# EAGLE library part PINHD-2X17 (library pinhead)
PIN HEADER
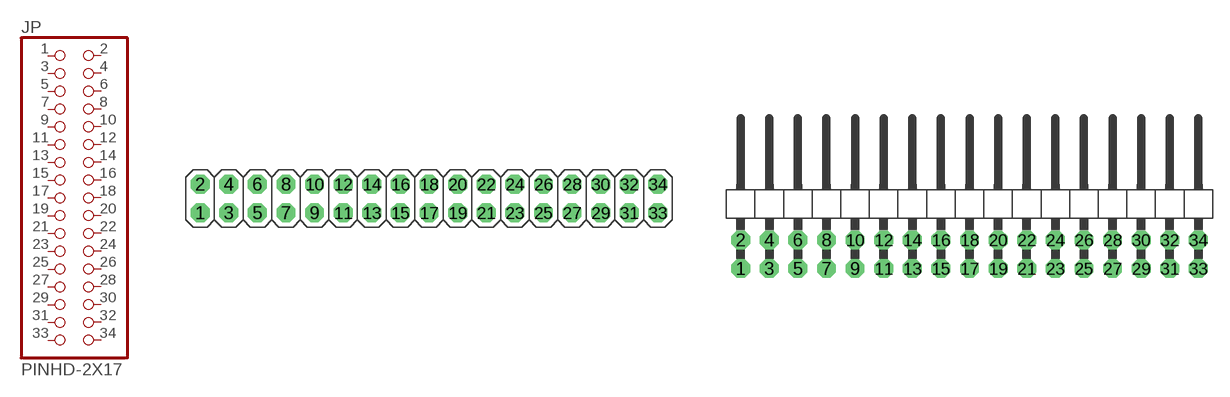
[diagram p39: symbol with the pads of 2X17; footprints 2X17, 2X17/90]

Designator prefix JP

## PINHD-2X17  [2X17]
1  1  pas
2  2  pas
3  3  pas
4  4  pas
5  5  pas
6  6  pas
7  7  pas
8  8  pas
9  9  pas
10  10  pas
11  11  pas
12  12  pas
13  13  pas
14  14  pas
15  15  pas
16  16  pas
17  17  pas
18  18  pas
19  19  pas
20  20  pas
21  21  pas
22  22  pas
23  23  pas
24  24  pas
25  25  pas
26  26  pas
27  27  pas
28  28  pas
29  29  pas
30  30  pas
31  31  pas
32  32  pas
33  33  pas
34  34  pas

## PINHD-2X17/90  [2X17/90]
Pads as for 2X17

## Footprint 2X17 (pad centres in mm)
PIN HEADER
drill 1.016 pad 1.67 octagon: 1 -20.32,-1.27; 2 -20.32,1.27; 3 -17.78,-1.27; 4 -17.78,1.27; 5 -15.24,-1.27; 6 -15.24,1.27; 7 -12.7,-1.27; 8 -12.7,1.27; 9 -10.16,-1.27; 10 -10.16,1.27; 11 -7.62,-1.27; 12 -7.62,1.27; 13 -5.08,-1.27; 14 -5.08,1.27; 15 -2.54,-1.27; 16 -2.54,1.27; 17 0,-1.27; 18 0,1.27; 19 2.54,-1.27; 20 2.54,1.27; 21 5.08,-1.27; 22 5.08,1.27; 23 7.62,-1.27; 24 7.62,1.27; 25 10.16,-1.27; 26 10.16,1.27; 27 12.7,-1.27; 28 12.7,1.27; 29 15.24,-1.27; 30 15.24,1.27; 31 17.78,-1.27; 32 17.78,1.27; 33 20.32,-1.27; 34 20.32,1.27

## Footprint 2X17/90 (pad centres in mm)
PIN HEADER
drill 1.016 pad 1.67 octagon: 1 -20.32,-6.35; 2 -20.32,-3.81; 3 -17.78,-6.35; 4 -17.78,-3.81; 5 -15.24,-6.35; 6 -15.24,-3.81; 7 -12.7,-6.35; 8 -12.7,-3.81; 9 -10.16,-6.35; 10 -10.16,-3.81; 11 -7.62,-6.35; 12 -7.62,-3.81; 13 -5.08,-6.35; 14 -5.08,-3.81; 15 -2.54,-6.35; 16 -2.54,-3.81; 17 0,-6.35; 18 0,-3.81; 19 2.54,-6.35; 20 2.54,-3.81; 21 5.08,-6.35; 22 5.08,-3.81; 23 7.62,-6.35; 24 7.62,-3.81; 25 10.16,-6.35; 26 10.16,-3.81; 27 12.7,-6.35; 28 12.7,-3.81; 29 15.24,-6.35; 30 15.24,-3.81; 31 17.78,-6.35; 32 17.78,-3.81; 33 20.32,-6.35; 34 20.32,-3.81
